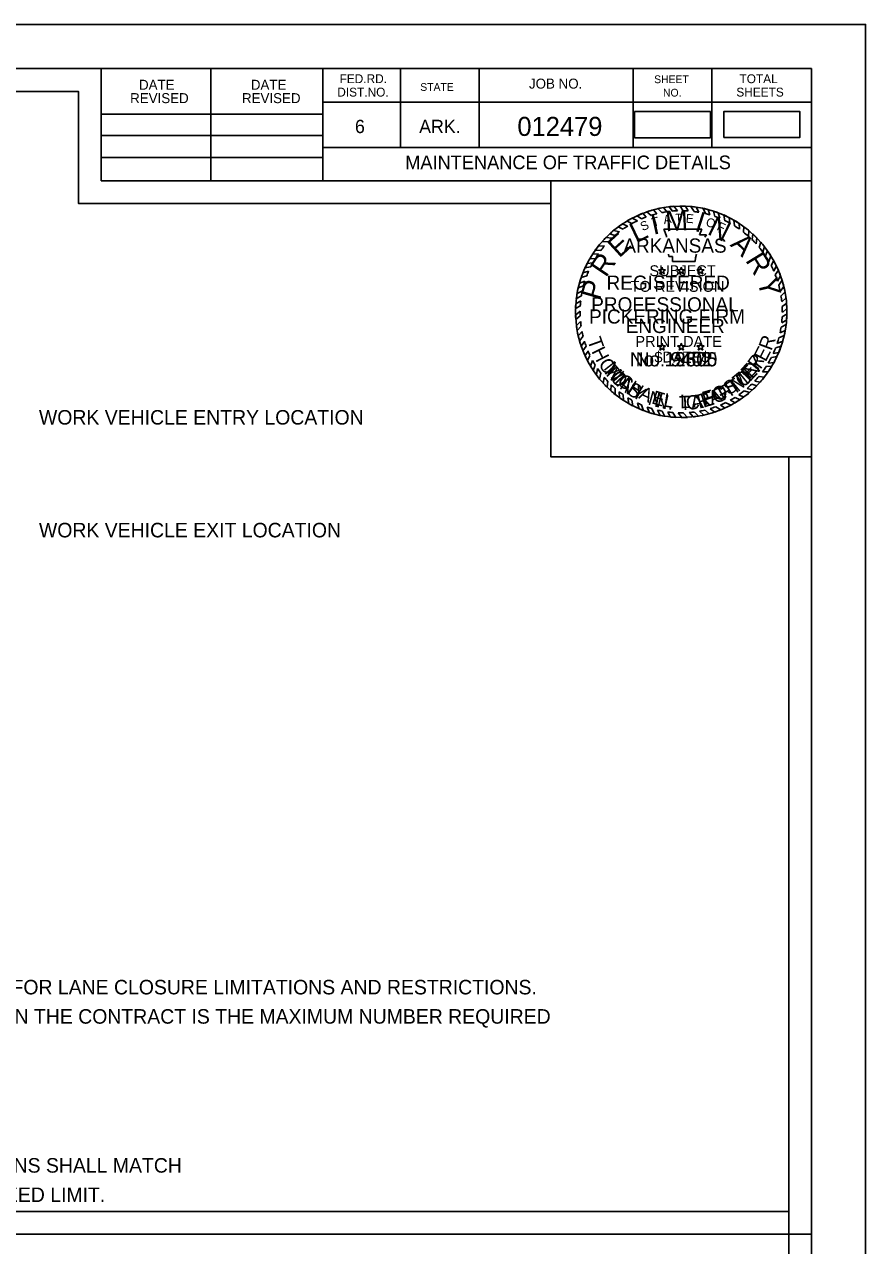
# Model space of a CAD drawing. Extents: x 1373222 to 1374279, y 380783 to 380996.
# Drawn here: x 1374204.6 to 1374278.7, y 380888.9 to 380996.5 of the extents above; entities that cross this region are included whole.
import ezdxf

# ---------------------------------------------------------------- set-up
doc = ezdxf.new("R2010")
doc.units = 0
for name, color, linetype in [('Default', 7, 'Continuous'), ('R_Border', 7, 'Continuous'), ('R_Border Notes', 7, 'Continuous'), ('R_Border Plan-Plan', 7, 'Continuous'), ('R_Draft', 7, 'Continuous'), ('R_No Plot', 7, 'Continuous'), ('STAMP_PE_CRAFTON', 7, 'Continuous'), ('STAMP_PE_FOSTER', 7, 'Continuous'), ('STAMP_PE_SEAL-INFO', 7, 'Continuous'), ('STAMP_PE_TAEGTMEYER', 7, 'Continuous'), ('STAMP_PE_TXT', 7, 'Continuous'), ('STAMP_PRELIMINARY', 7, 'Continuous')]:
    doc.layers.add(name, color=color, linetype=linetype)

msp = doc.modelspace()

# ---------------------------------------------------------------- linework, layer by layer
at = {"layer": 'Default'}
for points in [[(1374258.38, 380986.5), (1374265.07, 380986.5), (1374265.07, 380988.81), (1374258.38, 380988.81)], [(1374266.25, 380986.51), (1374272.94, 380986.51), (1374272.94, 380988.82), (1374266.25, 380988.82)]]:
    msp.add_lwpolyline(points, close=True, dxfattribs=at)
at = {"layer": 'R_Border'}
for p, q in [((1373957.81, 380992.59), (1374273.99, 380992.59)), ((1374211.35, 380982.71), (1374211.35, 380992.59)), ((1374221.03, 380982.71), (1374221.03, 380992.59)), ((1374230.89, 380992.59), (1374230.89, 380982.71)), ((1374237.73, 380992.59), (1374237.73, 380985.65)), ((1374244.67, 380992.59), (1374244.67, 380985.65)), ((1374258.25, 380992.59), (1374258.25, 380985.65)), ((1374265.19, 380992.59), (1374265.19, 380985.65)), ((1374273.99, 380787.13), (1374273.99, 380992.59)), ((1374273.99, 380989.65), (1374230.89, 380989.65)), ((1374273.99, 380989.67), (1374273.99, 380989.67)), ((1374211.35, 380988.57), (1374230.89, 380988.57)), ((1374211.35, 380986.71), (1374230.89, 380986.71)), ((1374273.99, 380985.65), (1374230.89, 380985.65)), ((1374233.85, 380985.65), (1374273.99, 380985.65)), ((1374211.35, 380984.77), (1374230.89, 380984.77)), ((1374273.99, 380982.71), (1374211.35, 380982.71))]:
    msp.add_line(p, q, dxfattribs=at)
at = {"layer": 'R_Border Plan-Plan'}
msp.add_line((1373957.81, 380889.86), (1374273.99, 380889.86), dxfattribs=at)
at = {"layer": 'R_No Plot'}
for points in [[(1373945.41, 380996.49), (1374278.75, 380996.49), (1374278.75, 380783.15), (1373945.41, 380783.15)], [(1374271.99, 380891.86), (1373959.81, 380891.86), (1373959.81, 380990.59), (1374209.35, 380990.59), (1374209.35, 380980.71), (1374226.89, 380980.71), (1374250.99, 380980.71), (1374250.99, 380958.38), (1374271.99, 380958.38)], [(1373959.81, 380990.59), (1374209.35, 380990.59), (1374209.35, 380980.71), (1374226.89, 380980.71), (1374250.99, 380980.71), (1374250.99, 380958.38), (1374271.99, 380958.38), (1374271.99, 380789.13), (1373959.81, 380789.13)], [(1374250.99, 380982.71), (1374273.99, 380982.71), (1374273.99, 380958.38), (1374250.99, 380958.38)]]:
    msp.add_lwpolyline(points, close=True, dxfattribs=at)
at = {"layer": 'STAMP_PE_SEAL-INFO'}
for p, q in [((1374258.6, 380979.62), (1374258.99, 380979.35)), ((1374259.11, 380979.84), (1374259.4, 380979.51)), ((1374259.45, 380979.97), (1374259.83, 380979.66)), ((1374260.04, 380980.15), (1374260.33, 380979.8)), ((1374260.43, 380980.25), (1374260.79, 380979.9)), ((1374260.92, 380980.34), (1374261.21, 380979.98)), ((1374261.43, 380980.42), (1374261.71, 380980.03)), ((1374262.17, 380980.06), (1374261.85, 380980.46)), ((1374262.66, 380980.07), (1374262.39, 380980.48)), ((1374263.12, 380980.05), (1374262.86, 380980.47)), ((1374263.63, 380980), (1374263.34, 380980.44)), ((1374264.05, 380979.93), (1374263.8, 380980.39)), ((1374264.62, 380979.81), (1374264.44, 380980.27)), ((1374265.02, 380979.7), (1374264.86, 380980.17)), ((1374265.47, 380979.56), (1374265.33, 380980.04)), ((1374265.89, 380979.4), (1374265.74, 380979.89)), ((1374266.35, 380979.19), (1374266.25, 380979.69)), ((1374266.79, 380978.96), (1374266.71, 380979.47)), ((1374256.91, 380978.65), (1374257.37, 380978.45)), ((1374257.33, 380978.92), (1374257.77, 380978.72)), ((1374257.72, 380979.16), (1374258.15, 380978.94)), ((1374258.17, 380979.41), (1374258.63, 380979.19)), ((1374260.97, 380978.45), (1374264.31, 380978.45)), ((1374261.09, 380978.14), (1374260.97, 380978.45)), ((1374264.31, 380978.45), (1374264.09, 380977.95)), ((1374267.18, 380978.74), (1374267.14, 380979.24)), ((1374267.62, 380978.45), (1374267.59, 380978.96)), ((1374267.98, 380978.18), (1374268.01, 380978.67)), ((1374255.53, 380977.36), (1374256.05, 380977.32)), ((1374255.86, 380977.7), (1374256.4, 380977.66)), ((1374256.19, 380978.02), (1374256.65, 380977.89)), ((1374256.54, 380978.32), (1374257.06, 380978.22)), ((1374261.19, 380977.84), (1374261.09, 380978.14)), ((1374261.2, 380977.73), (1374261.19, 380977.84)), ((1374264.09, 380977.95), (1374264.72, 380977.95)), ((1374264.72, 380977.95), (1374264.57, 380977.73)), ((1374268.42, 380977.81), (1374268.44, 380978.33)), ((1374268.74, 380977.52), (1374268.81, 380978.02)), ((1374269.1, 380977.14), (1374269.16, 380977.67)), ((1374254.67, 380976.23), (1374255.19, 380976.27)), ((1374254.91, 380976.58), (1374255.41, 380976.57)), ((1374255.19, 380976.95), (1374255.74, 380976.97)), ((1374261.39, 380976.02), (1374261.36, 380976.24)), ((1374263.83, 380976.24), (1374263.75, 380975.93)), ((1374269.37, 380976.83), (1374269.51, 380977.3)), ((1374269.69, 380976.41), (1374269.83, 380976.91)), ((1374269.91, 380976.1), (1374270.09, 380976.56)), ((1374254.2, 380975.41), (1374254.7, 380975.47)), ((1374254.43, 380975.83), (1374254.92, 380975.85)), ((1374261.71, 380976.02), (1374261.39, 380976.02)), ((1374261.71, 380975.59), (1374261.71, 380976.02)), ((1374263.73, 380975.59), (1374261.71, 380975.59)), ((1374263.75, 380975.93), (1374263.73, 380975.59)), ((1374270.22, 380975.6), (1374270.4, 380976.09)), ((1374270.42, 380975.23), (1374270.65, 380975.68)), ((1374270.65, 380974.75), (1374270.88, 380975.23)), ((1374253.68, 380974.18), (1374254.16, 380974.32)), ((1374253.83, 380974.59), (1374254.33, 380974.73)), ((1374254.01, 380975.02), (1374254.51, 380975.12)), ((1374270.79, 380974.41), (1374271.06, 380974.84)), ((1374270.99, 380973.86), (1374271.26, 380974.34)), ((1374253.78, 380973.02), (1374253.31, 380972.77)), ((1374253.41, 380973.27), (1374253.88, 380973.46)), ((1374253.52, 380973.68), (1374254, 380973.85)), ((1374271.09, 380973.5), (1374271.39, 380973.95)), ((1374271.23, 380972.94), (1374271.55, 380973.39)), ((1374253.63, 380972.13), (1374253.2, 380971.85)), ((1374253.69, 380972.56), (1374253.25, 380972.34)), ((1374271.3, 380972.56), (1374271.65, 380972.91)), ((1374271.36, 380972.05), (1374271.74, 380972.39)), ((1374271.4, 380971.63), (1374271.79, 380971.92)), ((1374253.6, 380971.7), (1374253.18, 380971.45)), ((1374253.58, 380971.21), (1374253.18, 380970.87)), ((1374271.4, 380970.71), (1374271.82, 380970.99)), ((1374271.41, 380971.11), (1374271.81, 380971.44)), ((1374253.59, 380970.8), (1374253.2, 380970.48)), ((1374253.62, 380970.31), (1374253.25, 380969.95)), ((1374253.67, 380969.88), (1374253.32, 380969.51)), ((1374271.31, 380969.81), (1374271.75, 380970.03)), ((1374271.36, 380970.2), (1374271.79, 380970.46)), ((1374253.75, 380969.42), (1374253.41, 380969.05)), ((1374253.85, 380969), (1374253.53, 380968.59)), ((1374271.11, 380968.86), (1374271.58, 380969.06)), ((1374271.22, 380969.31), (1374271.67, 380969.51)), ((1374253.97, 380968.55), (1374253.67, 380968.14)), ((1374254.11, 380968.13), (1374253.83, 380967.72)), ((1374254.28, 380967.7), (1374254.01, 380967.28)), ((1374270.83, 380967.99), (1374271.31, 380968.12)), ((1374270.96, 380968.37), (1374271.45, 380968.57)), ((1374254.45, 380967.32), (1374254.22, 380966.86)), ((1374254.68, 380966.86), (1374254.49, 380966.37)), ((1374270.18, 380966.64), (1374270.68, 380966.69)), ((1374270.45, 380967.14), (1374270.94, 380967.21)), ((1374270.61, 380967.47), (1374271.1, 380967.57)), ((1374254.92, 380966.46), (1374254.73, 380965.99)), ((1374255.12, 380966.15), (1374255.01, 380965.6)), ((1374255.4, 380965.76), (1374255.3, 380965.23)), ((1374269.36, 380965.47), (1374269.82, 380965.39)), ((1374269.67, 380965.86), (1374270.17, 380965.87)), ((1374270.01, 380966.36), (1374270.48, 380966.35)), ((1374255.71, 380965.38), (1374255.62, 380964.86)), ((1374256.01, 380965.04), (1374255.95, 380964.52)), ((1374256.33, 380964.72), (1374256.3, 380964.19)), ((1374256.67, 380964.4), (1374256.67, 380963.87)), ((1374268.32, 380964.4), (1374268.79, 380964.28)), ((1374268.72, 380964.78), (1374269.16, 380964.64)), ((1374268.98, 380965.04), (1374269.45, 380964.95)), ((1374257.03, 380964.11), (1374257.05, 380963.58)), ((1374257.37, 380963.86), (1374257.41, 380963.34)), ((1374257.8, 380963.58), (1374257.86, 380963.07)), ((1374258.15, 380963.37), (1374258.24, 380962.86)), ((1374266.83, 380963.36), (1374267.24, 380963.13)), ((1374267.24, 380963.61), (1374267.69, 380963.41)), ((1374267.58, 380963.84), (1374268.02, 380963.65)), ((1374268.04, 380964.18), (1374268.51, 380964.04)), ((1374258.63, 380963.12), (1374258.79, 380962.6)), ((1374259, 380962.95), (1374259.18, 380962.44)), ((1374259.5, 380962.76), (1374259.71, 380962.26)), ((1374259.91, 380962.63), (1374260.13, 380962.14)), ((1374260.41, 380962.49), (1374260.63, 380962.02)), ((1374260.81, 380962.4), (1374261.06, 380961.94)), ((1374261.31, 380962.32), (1374261.55, 380961.88)), ((1374261.75, 380962.27), (1374262.02, 380961.84)), ((1374262.23, 380962.25), (1374262.54, 380961.83)), ((1374262.69, 380962.24), (1374263.04, 380961.85)), ((1374263.21, 380962.27), (1374263.54, 380961.89)), ((1374263.65, 380962.32), (1374264.02, 380961.96)), ((1374264.1, 380962.39), (1374264.48, 380962.05)), ((1374264.59, 380962.49), (1374264.97, 380962.17)), ((1374265.05, 380962.61), (1374265.46, 380962.32)), ((1374265.54, 380962.78), (1374265.98, 380962.51)), ((1374265.96, 380962.94), (1374266.38, 380962.68)), ((1374266.42, 380963.15), (1374266.9, 380962.94))]:
    msp.add_line(p, q, dxfattribs=at)
for radius, start, end in [(9.32, 111.3124, 114.7026), (8.91, 110.3086, 113.1659), (9.32, 105.2339, 109.0352), (8.91, 104.0352, 107.3615), (9.32, 99.7525, 102.7765), (8.91, 98.258, 101.0329), (9.32, 93.9381, 96.5517), (8.91, 92.1102, 95.0367), (9.32, 87.7298, 90.6707), (8.91, 85.9628, 88.9097), (9.32, 81.9732, 84.8236), (8.91, 79.9264, 82.696), (9.32, 75.3125, 77.9426), (8.91, 73.5575, 76.2314), (9.32, 69.6061, 72.3058), (8.91, 67.6248, 70.504), (9.32, 63.1329, 66.2704), (9.32, 123.6199, 126.5906), (8.91, 121.9746, 125.11), (9.32, 117.6544, 120.8099), (8.91, 115.6869, 119.1583), (8.91, 61.1558, 64.3784), (9.32, 56.9003, 60.0942), (8.91, 54.9238, 58.2702), (9.32, 50.3492, 53.7159), (9.32, 135.4021, 138.3031), (8.91, 133.1331, 136.2562), (9.32, 129.7326, 132.5376), (8.91, 127.5297, 130.9683), (8.91, 48.3016, 52.0395), (8.91, 42.2212, 45.5512), (9.32, 44.3405, 47.3929), (9.32, 147.0072, 149.899), (9.32, 141.6056, 144.4486), (8.91, 145.0197, 148.2104), (8.91, 139.301, 142.5873), (8.91, 36.135, 39.5311), (9.32, 38.1247, 41.2316), (9.32, 31.9614, 35.4294), (9.32, 152.864, 155.5189), (8.91, 151.0315, 153.573), (8.91, 29.9032, 33.6645), (8.91, 23.7732, 27.2211), (9.32, 25.9391, 29.0125), (9.32, 158.4077, 161.0701), (8.91, 156.3402, 159.2319), (8.91, 17.6802, 21.4251), (9.32, 19.9538, 23.3141), (9.32, 164.3068, 166.894), (8.91, 167.9048, 170.9039), (8.91, 162.4331, 165.0013), (8.91, 11.5444, 15.2364), (9.32, 13.8421, 17.4447), (9.32, 170.0003, 172.6878), (8.91, 173.73, 176.4734), (8.91, 5.7599, 9.0606), (9.32, 7.5852, 10.8621), (9.32, 1.7215, 4.7268), (9.32, 175.7409, 178.2066), (9.32, 181.7251, 184.1626), (8.91, 179.6454, 182.2633), (8.91, 359.7329, 3.0639), (9.32, 355.7156, 358.9569), (9.32, 187.4204, 190.1927), (8.91, 185.4539, 188.234), (8.91, 348.0778, 351.3435), (8.91, 353.8632, 357.1274), (9.32, 349.8305, 353.0885), (9.32, 193.0369, 195.9973), (8.91, 191.2274, 193.9858), (8.91, 341.777, 345.0925), (9.32, 343.8925, 347.035), (9.32, 198.8967, 201.6281), (8.91, 196.9675, 199.8353), (8.91, 202.7761, 205.4791), (8.91, 335.6038, 339.1858), (9.32, 337.3837, 340.9933), (9.32, 204.5479, 207.4328), (8.91, 208.7883, 211.7934), (8.91, 329.5549, 333.2076), (9.32, 331.4037, 334.9332), (9.32, 210.8636, 213.6571), (9.32, 216.6115, 219.491), (8.91, 214.1838, 217.2747), (8.91, 316.6531, 320.3711), (8.91, 323.5851, 327.4407), (9.32, 325.4405, 328.9872), (9.32, 222.48, 225.3801), (8.91, 220.3909, 223.3056), (8.91, 226.2494, 229.2407), (8.91, 310.7744, 314.3161), (9.32, 312.4518, 315.6633), (9.32, 318.2846, 321.8043), (9.32, 228.3665, 231.348), (8.91, 232.229, 234.9336), (9.32, 234.295, 236.9452), (8.91, 238.2223, 240.8353), (8.91, 299.0768, 302.1724), (9.32, 300.621, 303.8703), (8.91, 304.823, 308.5143), (9.32, 306.3721, 310.208), (9.32, 240.1977, 242.8613), (8.91, 244.3204, 246.9486), (9.32, 246.576, 249.1558), (8.91, 250.3491, 253.1216), (9.32, 252.5967, 255.3252), (8.91, 256.505, 259.1192), (8.91, 262.3783, 265.2012), (8.91, 268.3215, 271.277), (8.91, 274.6157, 277.4486), (8.91, 280.3459, 283.5814), (8.91, 286.6423, 289.9783), (9.32, 288.5709, 291.9733), (8.91, 292.8745, 296.1185), (9.32, 294.6481, 298.2166), (9.32, 258.4433, 261.1398), (9.32, 264.1978, 267.1009), (9.32, 270.2548, 273.3361), (9.32, 276.4239, 279.4357), (9.32, 282.3199, 285.3702)]:
    msp.add_arc((1374262.49, 380971.16), radius, start, end, dxfattribs=at)
at = {"layer": 'STAMP_PE_TXT'}
for p, q in [((1374260.67, 380974.73), (1374260.48, 380974.87)), ((1374260.48, 380974.87), (1374260.72, 380974.87)), ((1374260.6, 380974.49), (1374260.67, 380974.73)), ((1374260.8, 380974.64), (1374260.6, 380974.49)), ((1374260.72, 380974.87), (1374260.8, 380975.1)), ((1374260.8, 380975.1), (1374260.87, 380974.87)), ((1374260.99, 380974.49), (1374260.8, 380974.64)), ((1374260.87, 380974.87), (1374261.12, 380974.87)), ((1374261.12, 380974.87), (1374260.92, 380974.73)), ((1374260.92, 380974.73), (1374260.99, 380974.49)), ((1374262.37, 380974.73), (1374262.17, 380974.87)), ((1374262.17, 380974.87), (1374262.42, 380974.87)), ((1374262.3, 380974.49), (1374262.37, 380974.73)), ((1374262.49, 380974.64), (1374262.3, 380974.49)), ((1374262.42, 380974.87), (1374262.49, 380975.1)), ((1374262.49, 380975.1), (1374262.57, 380974.87)), ((1374262.69, 380974.49), (1374262.49, 380974.64)), ((1374262.57, 380974.87), (1374262.82, 380974.87)), ((1374262.82, 380974.87), (1374262.62, 380974.73)), ((1374262.62, 380974.73), (1374262.69, 380974.49)), ((1374264.07, 380974.73), (1374263.87, 380974.87)), ((1374263.87, 380974.87), (1374264.12, 380974.87)), ((1374263.99, 380974.49), (1374264.07, 380974.73)), ((1374264.19, 380974.64), (1374263.99, 380974.49)), ((1374264.12, 380974.87), (1374264.19, 380975.1)), ((1374264.19, 380975.1), (1374264.27, 380974.87)), ((1374264.39, 380974.49), (1374264.19, 380974.64)), ((1374264.27, 380974.87), (1374264.51, 380974.87)), ((1374264.51, 380974.87), (1374264.31, 380974.73)), ((1374264.31, 380974.73), (1374264.39, 380974.49)), ((1374260.67, 380968.02), (1374260.48, 380968.16)), ((1374260.48, 380968.16), (1374260.72, 380968.16)), ((1374260.6, 380967.79), (1374260.67, 380968.02)), ((1374260.8, 380967.93), (1374260.6, 380967.79)), ((1374260.72, 380968.16), (1374260.8, 380968.4)), ((1374260.8, 380968.4), (1374260.87, 380968.16)), ((1374260.99, 380967.79), (1374260.8, 380967.93)), ((1374260.87, 380968.16), (1374261.12, 380968.16)), ((1374261.12, 380968.16), (1374260.92, 380968.02)), ((1374260.92, 380968.02), (1374260.99, 380967.79)), ((1374262.37, 380968.02), (1374262.17, 380968.16)), ((1374262.17, 380968.16), (1374262.42, 380968.16)), ((1374262.3, 380967.79), (1374262.37, 380968.02)), ((1374262.49, 380967.93), (1374262.3, 380967.79)), ((1374262.42, 380968.16), (1374262.49, 380968.4)), ((1374262.49, 380968.4), (1374262.57, 380968.16)), ((1374262.69, 380967.79), (1374262.49, 380967.93)), ((1374262.57, 380968.16), (1374262.82, 380968.16)), ((1374262.82, 380968.16), (1374262.62, 380968.02)), ((1374262.62, 380968.02), (1374262.69, 380967.79)), ((1374264.07, 380968.02), (1374263.87, 380968.16)), ((1374263.87, 380968.16), (1374264.12, 380968.16)), ((1374263.99, 380967.79), (1374264.07, 380968.02)), ((1374264.19, 380967.93), (1374263.99, 380967.79)), ((1374264.12, 380968.16), (1374264.19, 380968.4)), ((1374264.19, 380968.4), (1374264.27, 380968.16)), ((1374264.39, 380967.79), (1374264.19, 380967.93)), ((1374264.27, 380968.16), (1374264.51, 380968.16)), ((1374264.51, 380968.16), (1374264.31, 380968.02)), ((1374264.31, 380968.02), (1374264.39, 380967.79))]:
    msp.add_line(p, q, dxfattribs=at)
at = {"layer": 'STAMP_PRELIMINARY'}
msp.add_circle((1374262.49, 380971.16), 9.32, dxfattribs=at)

# ---------------------------------------------------------------- texts
at = {"layer": 'R_Border'}
for s, height, p in [('DATE', 0.879, (1374214.69, 380990.73)), ('DATE', 0.879, (1374224.55, 380990.73)), ('FED.RD.', 0.782, (1374232.37, 380991.31)), ('STATE', 0.684, (1374239.49, 380990.63)), ('JOB NO.', 0.879, (1374249.07, 380990.83)), ('SHEET', 0.684, (1374260.11, 380991.31)), ('TOTAL', 0.782, (1374267.63, 380991.31)), ('REVISED', 0.879, (1374213.91, 380989.55)), ('REVISED', 0.879, (1374223.77, 380989.55)), ('DIST.NO.', 0.782, (1374232.17, 380990.13)), ('NO.', 0.684, (1374260.89, 380990.13)), ('SHEETS', 0.782, (1374267.35, 380990.13)), ('6', 1.17, (1374233.73, 380986.91)), ('ARK.', 1.172, (1374239.39, 380986.91))]:
    msp.add_text(s, height=height, dxfattribs=at).set_placement(p)
at = {"layer": 'R_Border Notes'}
for s, height, p in [('012479', 1.68, (1374248.05, 380986.66)), ('MAINTENANCE OF TRAFFIC DETAILS', 1.2, (1374238.16, 380983.73))]:
    msp.add_text(s, height=height, dxfattribs=at).set_placement(p)
at = {"layer": 'R_Draft'}
for s, p in [('WORK VEHICLE ENTRY LOCATION', (1374205.87, 380961.22)), ('WORK VEHICLE EXIT LOCATION', (1374205.87, 380951.28)), ('NOTE:  REFER TO SP-MAINTENANCE OF TRAFFIC FOR LANE CLOSURE LIMITATIONS AND RESTRICTIONS.  ', (1374161.8, 380911)), (' QUANTITY OF TRAFFIC DRUMS PROVIDED IN THE CONTRACT IS THE MAXIMUM NUMBER REQUIRED', (1374166.92, 380908.42))]:
    msp.add_text(s, height=1.28, dxfattribs=at).set_placement(p)
for s, p in [('*SPEED LIMIT SIGNS SHALL MATCH', (1374188.89, 380895.29)), (' PERMANENT SPEED LIMIT.', (1374188.89, 380892.7))]:
    msp.add_text(s, height=1.28, rotation=360, dxfattribs=at).set_placement(p)
at = {"layer": 'STAMP_PE_CRAFTON'}
msp.add_text('No. 12370', height=1.25, dxfattribs=at).set_placement((1374257.96, 380966.35))
for s, rotation, p in [('T', 310.7442, (1374255.46, 380966.05)), ('N', 49.2411, (1374268.78, 380965.18)), ('O', 317.6422, (1374256.13, 380965.24)), ('O', 41.8391, (1374267.93, 380964.4)), ('N', 324.4537, (1374256.97, 380964.46)), ('Y', 331.1686, (1374258.01, 380963.74)), ('F', 28.7821, (1374266.16, 380963.28)), ('T', 34.1136, (1374267.07, 380963.79)), ('N', 347.4752, (1374260.06, 380962.82)), ('C', 6.0117, (1374262.97, 380962.5)), ('R', 14.8189, (1374264.06, 380962.61)), ('A', 20.5125, (1374265.18, 380962.91)), ('.', 356.8926, (1374261.29, 380962.55))]:
    msp.add_text(s, height=1.25, rotation=rotation, dxfattribs=at).set_placement(p)
at = {"layer": 'STAMP_PE_FOSTER'}
msp.add_text('No. 9402', height=1.25, dxfattribs=at).set_placement((1374258.48, 380966.35))
for s, rotation, p in [('M', 308.339, (1374255.61, 380966.18)), ('E', 46.9613, (1374268.49, 380965.15)), ('R', 54.5031, (1374269.22, 380965.97)), ('I', 314.1842, (1374256.41, 380965.24)), ('C', 319.8733, (1374256.76, 380964.89)), ('T', 39.4194, (1374267.64, 380964.4)), ('H', 327.7235, (1374257.69, 380964.15)), ('A', 335.7276, (1374258.67, 380963.57)), ('O', 23.719, (1374265.57, 380963.24)), ('S', 31.7234, (1374266.68, 380963.77)), ('E', 343.5779, (1374259.81, 380963.1)), ('L', 350.8115, (1374260.87, 380962.82)), ('L', 1.2666, (1374262.41, 380962.66)), ('F', 15.8691, (1374264.53, 380962.91)), ('.', 6.8035, (1374263.45, 380962.72))]:
    msp.add_text(s, height=1.2, rotation=rotation, dxfattribs=at).set_placement(p)
at = {"layer": 'STAMP_PE_TAEGTMEYER'}
for s, rotation, p in [('T', 289.646, (1374254.19, 380968.67)), ('R', 69.57, (1374270.44, 380967.67)), ('H', 296.7339, (1374254.55, 380967.68)), ('E', 63.0984, (1374269.94, 380966.69)), ('O', 303.7708, (1374255.14, 380966.57)), ('Y', 53.9986, (1374269.27, 380965.75)), ('M', 314.2033, (1374255.8, 380965.62)), ('M', 39.3, (1374267.49, 380964.05)), ('E', 46.8094, (1374268.53, 380964.93)), ('A', 321.0594, (1374256.76, 380964.66)), ('S', 327.8239, (1374257.58, 380964.01)), ('G', 23.3052, (1374265.49, 380963.02)), ('T', 31.466, (1374266.59, 380963.51)), ('N', 344.2727, (1374259.48, 380963.01)), ('T', 3.0061, (1374262.36, 380962.48)), ('A', 8.9826, (1374263.41, 380962.53)), ('E', 17.6836, (1374264.44, 380962.69)), ('.', 350.6464, (1374260.69, 380962.67))]:
    msp.add_text(s, height=1.25, rotation=rotation, dxfattribs=at).set_placement(p)
msp.add_text('No. 19605', height=1.25, dxfattribs=at).set_placement((1374257.96, 380966.35))
at = {"layer": 'STAMP_PE_TXT'}
for s, rotation, p in [('T', 16.311, (1374260.02, 380978.63)), ('A', 9.0679, (1374260.98, 380978.88)), ('T', 1.8248, (1374261.96, 380979.01)), ('E', 355.2002, (1374262.87, 380979.02)), ('S', 23.5541, (1374259.09, 380978.26)), ('O', 342.2506, (1374264.6, 380978.75)), ('F', 335.0075, (1374265.57, 380978.41))]:
    msp.add_text(s, height=0.781, rotation=rotation, dxfattribs=at).set_placement(p)
for s, p in [('ARKANSAS', (1374257.39, 380976.37)), ('REGISTERED', (1374255.91, 380973.1)), ('PROFESSIONAL', (1374254.56, 380971.19)), ('ENGINEER', (1374257.6, 380969.29))]:
    msp.add_text(s, height=1.25, dxfattribs=at).set_placement(p)
at = {"layer": 'STAMP_PRELIMINARY'}
for s, rotation, p in [('I', 12.5248, (1374260.03, 380977.94)), ('M', 3.1074, (1374261.13, 380978.25)), ('I', 342.3164, (1374263.6, 380978.32)), ('N', 333.9382, (1374264.71, 380978.04)), ('L', 25.513, (1374258.5, 380977.18)), ('E', 42.3578, (1374257.02, 380975.85)), ('A', 315.6579, (1374266.74, 380977.02)), ('R', 56.2292, (1374255.86, 380974.12)), ('R', 301.3831, (1374268.11, 380975.7)), ('Y', 283.2593, (1374269.2, 380973.92)), ('P', 73.913, (1374255.32, 380972.1))]:
    msp.add_text(s, height=1.8, rotation=rotation, dxfattribs=at).set_placement(p)
for s, height, p in [('SUBJECT', 0.96, (1374259.69, 380974.3)), ('TO REVISION', 0.96, (1374258.03, 380972.92)), ('PICKERING FIRM', 1.25, (1374254.37, 380970.12)), ('PRINT DATE', 0.96, (1374258.45, 380968.07)), ('$DATE$', 0.96, (1374260.13, 380966.69))]:
    msp.add_text(s, height=height, dxfattribs=at).set_placement(p)

doc.saveas('drawing.dxf')
